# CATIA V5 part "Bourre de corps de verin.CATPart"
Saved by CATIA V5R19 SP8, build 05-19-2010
Part number: Bourre
Revision: ANY
Definition: UNKNOWN
Nomenclature: Bourre de corps de verin
Source: Unknown
Bounding box of the stored display mesh (mm): x -6.25 to 6.25, y -6.25 to 6.25, z 0 to 15
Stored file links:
  D:\Documents\1_Travail\1 - ac-limoges.fr\ac-limoges.fr\Emmanuel Maynard - STI2D_Turgot\2 -2I2D\3_SEQUENCE_Serre_Connectée\Dossier technique_SERRE\Maquettes_CATIA\Vérin_Thermodynamique\Bourre de corps de verin.CATPart
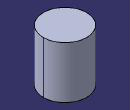
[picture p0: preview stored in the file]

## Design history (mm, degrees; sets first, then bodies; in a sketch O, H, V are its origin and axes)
Body1 "NONE" (main body)
  Solid1: solid without history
